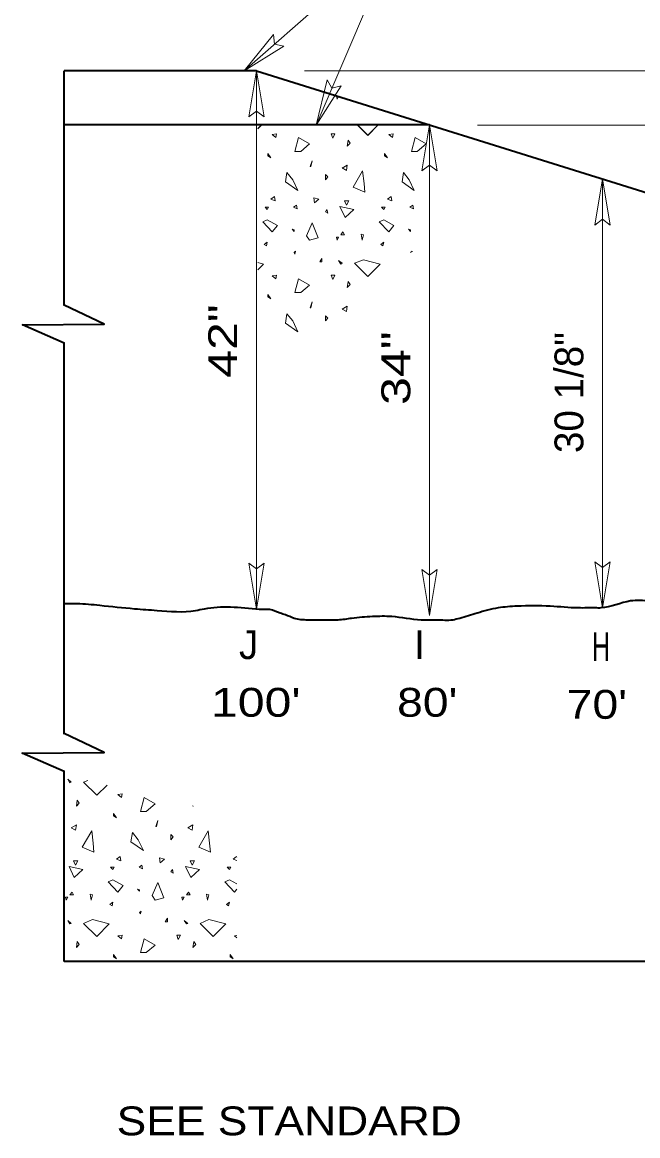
# Model space of a CAD drawing. Extents: x -15.1 to -7.9, y 13.6 to 23.8.
# Drawn here: x -15.003 to -13.723, y 19.682 to 21.999 of the extents above; entities that cross this region are included whole.
import ezdxf
from ezdxf.enums import TextEntityAlignment as Align

# ---------------------------------------------------------------- set-up
doc = ezdxf.new("R2010")
doc.units = 0
doc.header["$LTSCALE"] = 0.024
for name, color, linetype, lineweight in [('1', 7, 'Continuous', 35), ('10', 7, 'Continuous', 13), ('12', 7, 'Continuous', 53), ('6', 7, 'Continuous', 13)]:
    doc.layers.add(name, color=color, linetype=linetype, lineweight=lineweight)

msp = doc.modelspace()

# ---------------------------------------------------------------- linework, layer by layer
at = {"layer": '1'}
for p, q in [((-14.51633, 21.89767), (-14.91633, 21.89767)), ((-14.51633, 21.89767), (-11.27283, 20.88417)), ((-14.15633, 21.78517), (-14.91633, 21.78517)), ((-14.1535, 21.78433), (-14.15333, 21.78433)), ((-11.993, 20.044), (-14.91633, 20.044))]:
    msp.add_line(p, q, dxfattribs=at)
for points in [[(-14.51033, 20.77633), (-14.57033, 20.78117), (-14.62483, 20.77767), (-14.64283, 20.774), (-14.72267, 20.774), (-14.76967, 20.77767), (-14.84217, 20.78483), (-14.88933, 20.7885), (-14.91633, 20.7885)], [(-11.993, 20.76417), (-12.053, 20.769), (-12.1075, 20.7655), (-12.1255, 20.76183), (-12.20533, 20.76183), (-12.25233, 20.7655), (-12.32483, 20.77267), (-12.372, 20.77633), (-12.41917, 20.77633), (-12.46267, 20.77633), (-12.5025, 20.77267), (-12.58583, 20.7655), (-12.6185, 20.7655), (-12.65833, 20.7655), (-12.6945, 20.7655), (-12.72717, 20.77267), (-12.7635, 20.77633), (-12.78883, 20.77983), (-12.84683, 20.79067), (-12.883, 20.79067), (-12.93017, 20.79433), (-12.96283, 20.79067), (-13.028, 20.77983), (-13.0425, 20.77983), (-13.09317, 20.77633), (-13.11867, 20.77633), (-13.1585, 20.77633), (-13.202, 20.7835), (-13.23817, 20.79067), (-13.28167, 20.79433), (-13.32883, 20.79067), (-13.3615, 20.79067), (-13.41217, 20.77633), (-13.43033, 20.77633), (-13.47017, 20.77267), (-13.52083, 20.77983), (-13.5535, 20.7835), (-13.61517, 20.78717), (-13.64417, 20.79067), (-13.6985, 20.79433), (-13.73833, 20.79433), (-13.8, 20.77983), (-13.81083, 20.77983), (-13.84717, 20.77983), (-13.90517, 20.7835), (-13.974, 20.7835), (-14.01383, 20.77983), (-14.05733, 20.769), (-14.0935, 20.75817), (-14.108, 20.75467), (-14.14067, 20.75467), (-14.17333, 20.75467), (-14.23483, 20.76183), (-14.27483, 20.76183), (-14.31833, 20.75817), (-14.34717, 20.75467), (-14.369, 20.75467), (-14.40883, 20.75467), (-14.43783, 20.75817), (-14.456, 20.7655), (-14.46683, 20.769), (-14.48867, 20.77633), (-14.50317, 20.77633), (-14.51033, 20.77633)]]:
    msp.add_spline(points, degree=3, dxfattribs=at)
at = {"layer": '10'}
for p, q in [((-14.22542, 22.17525), (-14.54208, 21.89767)), ((-14.22542, 22.17525), (-14.39208, 21.78433)), ((-14.48042, 21.973), (-14.54208, 21.89767)), ((-14.48042, 21.973), (-14.47892, 21.953)), ((-14.45933, 21.94892), (-14.54208, 21.89767)), ((-14.45933, 21.94892), (-14.47892, 21.953)), ((-14.53233, 21.80167), (-14.51633, 21.89767)), ((-14.50033, 21.80167), (-14.51633, 21.89767)), ((-14.51633, 20.77725), (-14.51633, 21.89767)), ((-14.41633, 21.89767), (-9.09375, 21.89767)), ((-14.36917, 21.87892), (-14.39208, 21.78433)), ((-14.36917, 21.87892), (-14.35917, 21.86158)), ((-14.33975, 21.86633), (-14.39208, 21.78433)), ((-14.33975, 21.86633), (-14.35917, 21.86158)), ((-14.53233, 21.80167), (-14.51633, 21.81367)), ((-14.50033, 21.80167), (-14.51633, 21.81367)), ((-14.17233, 21.68917), (-14.15633, 21.78517)), ((-14.15633, 20.76417), (-14.15633, 21.78517)), ((-14.14033, 21.68917), (-14.15633, 21.78517)), ((-14.05633, 21.78433), (-9.13367, 21.78433)), ((-14.17233, 21.68917), (-14.15633, 21.70117)), ((-14.14033, 21.68917), (-14.15633, 21.70117)), ((-13.81233, 21.57667), (-13.79633, 21.67267)), ((-13.78033, 21.57667), (-13.79633, 21.67267)), ((-13.79633, 20.78), (-13.79633, 21.67267)), ((-13.81233, 21.57667), (-13.79633, 21.58867)), ((-13.78033, 21.57667), (-13.79633, 21.58867)), ((-13.81233, 20.876), (-13.79633, 20.78)), ((-13.81233, 20.876), (-13.79633, 20.864)), ((-13.78033, 20.876), (-13.79633, 20.78)), ((-13.78033, 20.876), (-13.79633, 20.864)), ((-14.53233, 20.87325), (-14.51633, 20.77725)), ((-14.53233, 20.87325), (-14.51633, 20.86125)), ((-14.50033, 20.87325), (-14.51633, 20.77725)), ((-14.50033, 20.87325), (-14.51633, 20.86125)), ((-14.17233, 20.86017), (-14.15633, 20.76417)), ((-14.17233, 20.86017), (-14.15633, 20.84817)), ((-14.14033, 20.86017), (-14.15633, 20.76417)), ((-14.14033, 20.86017), (-14.15633, 20.84817))]:
    msp.add_line(p, q, dxfattribs=at)
at = {"layer": '10', "lineweight": 35}
for p, q in [((-14.91633, 21.40933), (-14.91633, 21.89767)), ((-14.91633, 20.51733), (-14.91633, 21.332)), ((-14.91633, 20.044), (-14.91633, 20.44067))]:
    msp.add_line(p, q, dxfattribs=at)
for points in [[(-14.91583, 21.33067), (-15.003, 21.36883), (-14.83267, 21.37017), (-14.91583, 21.40967)], [(-14.916, 20.4395), (-15.00317, 20.47767), (-14.83283, 20.479), (-14.916, 20.5185)]]:
    msp.add_lwpolyline(points, dxfattribs=at)
at = {"layer": '6'}
for p, q in [((-14.50633, 21.78433), (-14.5135, 21.77717)), ((-14.50517, 21.78517), (-14.51333, 21.77692))]:
    msp.add_line(p, q, dxfattribs=at)
for points in [[(-14.3475, 21.84492), (-14.35, 21.84492), (-14.35, 21.84492), (-14.34867, 21.83875), (-14.34567, 21.84433)], [(-14.26292, 21.78517), (-14.28483, 21.76308), (-14.30675, 21.78517)], [(-14.26333, 21.78483), (-14.28483, 21.76333), (-14.30633, 21.78483)], [(-14.19267, 21.52117), (-14.19233, 21.5225), (-14.1955, 21.51967)], [(-14.51333, 21.49867), (-14.50133, 21.4955), (-14.51333, 21.48333)], [(-14.82692, 20.41142), (-14.84825, 20.39008), (-14.87575, 20.41742), (-14.86692, 20.42108)], [(-14.64842, 20.36825), (-14.64842, 20.36742), (-14.64775, 20.36808)], [(-14.55708, 20.26108), (-14.55742, 20.26292), (-14.56492, 20.25692), (-14.55708, 20.25408)], [(-14.55708, 20.20558), (-14.57258, 20.21442), (-14.58192, 20.21008), (-14.56208, 20.18875), (-14.55708, 20.19492)], [(-14.55708, 20.09858), (-14.56208, 20.09775), (-14.55708, 20.09375)]]:
    msp.add_lwpolyline(points, dxfattribs=at)
for points in [[(-14.48333, 21.76483), (-14.47567, 21.75867), (-14.47433, 21.76633)], [(-14.42417, 21.72983), (-14.40583, 21.74533), (-14.4285, 21.75867), (-14.43617, 21.72983)], [(-14.3605, 21.76633), (-14.35767, 21.75733), (-14.353, 21.76633)], [(-14.241, 21.76483), (-14.23333, 21.75867), (-14.232, 21.76633)], [(-14.18183, 21.72983), (-14.1635, 21.74533), (-14.18617, 21.75867), (-14.19383, 21.72983)], [(-14.3255, 21.753), (-14.32733, 21.74067), (-14.32117, 21.74683)], [(-14.49233, 21.7255), (-14.49233, 21.72083), (-14.48617, 21.7165)], [(-14.40433, 21.69817), (-14.403, 21.69817), (-14.40017, 21.7105)], [(-14.25, 21.7255), (-14.25, 21.72083), (-14.24383, 21.7165)], [(-14.33783, 21.69533), (-14.32883, 21.69067), (-14.32733, 21.7015)], [(-14.33783, 21.69508), (-14.32883, 21.69042), (-14.32733, 21.70125)], [(-14.2925, 21.66333), (-14.291, 21.64533), (-14.31517, 21.65567), (-14.29533, 21.68917)], [(-14.453, 21.686), (-14.45583, 21.6665), (-14.43033, 21.64817), (-14.44083, 21.67083)], [(-14.37267, 21.68167), (-14.37267, 21.67083), (-14.368, 21.677)], [(-14.37267, 21.68142), (-14.37267, 21.67058), (-14.368, 21.67675)], [(-14.21067, 21.686), (-14.2135, 21.6665), (-14.188, 21.64817), (-14.1985, 21.67083)], [(-14.4785, 21.63633), (-14.48617, 21.63017), (-14.47717, 21.627)], [(-14.43933, 21.61367), (-14.43183, 21.61033), (-14.43317, 21.61783)], [(-14.39683, 21.633), (-14.39533, 21.62267), (-14.38633, 21.63017)], [(-14.33317, 21.627), (-14.32883, 21.61783), (-14.32417, 21.627)], [(-14.23633, 21.63633), (-14.24383, 21.63017), (-14.23483, 21.627)], [(-14.197, 21.61367), (-14.1895, 21.61033), (-14.19083, 21.61783)], [(-14.49833, 21.61367), (-14.49367, 21.60883), (-14.49083, 21.61367)], [(-14.37267, 21.60417), (-14.368, 21.60133), (-14.3695, 21.60883)], [(-14.3425, 21.615), (-14.33167, 21.59233), (-14.31367, 21.60883)], [(-14.256, 21.61367), (-14.25133, 21.60883), (-14.2485, 21.61367)], [(-14.503, 21.58333), (-14.48333, 21.56217), (-14.4725, 21.5755), (-14.49367, 21.58767)], [(-14.40583, 21.54517), (-14.38783, 21.54983), (-14.40017, 21.5815), (-14.412, 21.5545)], [(-14.26067, 21.58333), (-14.241, 21.56217), (-14.23017, 21.5755), (-14.25133, 21.58767)], [(-14.43783, 21.5665), (-14.44217, 21.56783), (-14.43783, 21.5635)], [(-14.35, 21.55133), (-14.34867, 21.54517), (-14.34533, 21.55133)], [(-14.33633, 21.56217), (-14.33317, 21.556), (-14.34067, 21.556)], [(-14.2985, 21.5575), (-14.29667, 21.54517), (-14.29383, 21.556)], [(-14.1955, 21.5665), (-14.19983, 21.56783), (-14.1955, 21.5635)], [(-14.49983, 21.53617), (-14.4955, 21.53333), (-14.49367, 21.54083)], [(-14.2575, 21.53617), (-14.25317, 21.53333), (-14.25133, 21.54083)], [(-14.43467, 21.5225), (-14.43783, 21.51967), (-14.43617, 21.51633)], [(-14.38033, 21.50733), (-14.38467, 21.49983), (-14.38033, 21.49983)], [(-14.34067, 21.4955), (-14.33783, 21.497), (-14.34533, 21.503)], [(-14.29383, 21.5045), (-14.259, 21.4955), (-14.28483, 21.4695), (-14.31217, 21.497)], [(-14.48333, 21.471), (-14.47567, 21.46483), (-14.47433, 21.4725)], [(-14.42417, 21.43617), (-14.40583, 21.4515), (-14.4285, 21.46483), (-14.43617, 21.43617)], [(-14.3605, 21.4725), (-14.35767, 21.4635), (-14.353, 21.4725)], [(-14.3255, 21.45917), (-14.32733, 21.44683), (-14.32117, 21.453)], [(-14.49233, 21.43183), (-14.49233, 21.42717), (-14.48617, 21.42283)], [(-14.40433, 21.40433), (-14.403, 21.40433), (-14.40017, 21.41667)], [(-14.453, 21.39217), (-14.45583, 21.37267), (-14.43033, 21.35433), (-14.44083, 21.377)], [(-14.37267, 21.38783), (-14.37267, 21.377), (-14.368, 21.38317)], [(-14.33783, 21.4015), (-14.32883, 21.39683), (-14.32733, 21.40767)], [(-14.90408, 20.41608), (-14.90125, 20.41742), (-14.90875, 20.42358)], [(-14.80442, 20.39158), (-14.79692, 20.38542), (-14.79542, 20.39292)], [(-14.88908, 20.37958), (-14.89075, 20.36742), (-14.88475, 20.37358)], [(-14.74542, 20.35658), (-14.72692, 20.37208), (-14.74975, 20.38542), (-14.75725, 20.35658)], [(-14.81342, 20.35225), (-14.81342, 20.34758), (-14.80725, 20.34325)], [(-14.90125, 20.32208), (-14.89225, 20.31742), (-14.89075, 20.32825)], [(-14.72558, 20.32492), (-14.72408, 20.32492), (-14.72125, 20.33725)], [(-14.65892, 20.32208), (-14.64992, 20.31742), (-14.64842, 20.32825)], [(-14.85592, 20.29008), (-14.85442, 20.27192), (-14.87858, 20.28242), (-14.85875, 20.31592)], [(-14.77408, 20.31275), (-14.77708, 20.29325), (-14.75142, 20.27492), (-14.76192, 20.29758)], [(-14.69392, 20.30842), (-14.69392, 20.29758), (-14.68925, 20.30375)], [(-14.61358, 20.29008), (-14.61208, 20.27192), (-14.63625, 20.28242), (-14.61642, 20.31592)], [(-14.89658, 20.25358), (-14.89225, 20.24458), (-14.88758, 20.25358)], [(-14.79975, 20.26292), (-14.80725, 20.25692), (-14.79825, 20.25358)], [(-14.71792, 20.25975), (-14.71658, 20.24925), (-14.70758, 20.25692)], [(-14.65425, 20.25358), (-14.64992, 20.24458), (-14.64525, 20.25358)], [(-14.90592, 20.24175), (-14.89508, 20.21908), (-14.87708, 20.23558)], [(-14.81958, 20.24025), (-14.81492, 20.23558), (-14.81192, 20.24025)], [(-14.76042, 20.24025), (-14.75292, 20.23708), (-14.75442, 20.24458)], [(-14.69392, 20.23092), (-14.68925, 20.22808), (-14.69058, 20.23558)], [(-14.66358, 20.24175), (-14.65275, 20.21908), (-14.63475, 20.23558)], [(-14.57725, 20.24025), (-14.57258, 20.23558), (-14.56958, 20.24025)], [(-14.82425, 20.21008), (-14.80442, 20.18875), (-14.79358, 20.20208), (-14.81492, 20.21442)], [(-14.72692, 20.17192), (-14.70892, 20.17658), (-14.72125, 20.20825), (-14.73308, 20.18125)], [(-14.89975, 20.18875), (-14.89658, 20.18275), (-14.90408, 20.18275)], [(-14.86208, 20.18408), (-14.86025, 20.17192), (-14.85725, 20.18275)], [(-14.75908, 20.19308), (-14.76342, 20.19458), (-14.75908, 20.19025)], [(-14.65742, 20.18875), (-14.65425, 20.18275), (-14.66175, 20.18275)], [(-14.61975, 20.18408), (-14.61792, 20.17192), (-14.61508, 20.18275)], [(-14.91342, 20.17808), (-14.91208, 20.17192), (-14.90875, 20.17808)], [(-14.82092, 20.16292), (-14.81658, 20.16008), (-14.81492, 20.16758)], [(-14.67125, 20.17808), (-14.66975, 20.17192), (-14.66642, 20.17808)], [(-14.57858, 20.16292), (-14.57425, 20.16008), (-14.57258, 20.16758)], [(-14.75575, 20.14925), (-14.75908, 20.14642), (-14.75725, 20.14308)], [(-14.70142, 20.13408), (-14.70575, 20.12658), (-14.70142, 20.12658)], [(-14.90408, 20.12225), (-14.90125, 20.12358), (-14.90875, 20.12975)], [(-14.85725, 20.13125), (-14.82242, 20.12225), (-14.84825, 20.09625), (-14.87575, 20.12358)], [(-14.66175, 20.12225), (-14.65892, 20.12358), (-14.66642, 20.12975)], [(-14.61508, 20.13125), (-14.58008, 20.12225), (-14.60608, 20.09625), (-14.63342, 20.12358)], [(-14.80442, 20.09775), (-14.79692, 20.09158), (-14.79542, 20.09925)], [(-14.74542, 20.06275), (-14.72692, 20.07825), (-14.74975, 20.09158), (-14.75725, 20.06275)], [(-14.68158, 20.09925), (-14.67875, 20.09025), (-14.67408, 20.09925)], [(-14.88908, 20.08592), (-14.89075, 20.07358), (-14.88475, 20.07975)], [(-14.64675, 20.08592), (-14.64842, 20.07358), (-14.64242, 20.07975)], [(-14.81342, 20.05842), (-14.81342, 20.05375), (-14.80725, 20.04942)], [(-14.57108, 20.05842), (-14.57108, 20.05375), (-14.56492, 20.04942)]]:
    msp.add_lwpolyline(points, close=True, dxfattribs=at)

# ---------------------------------------------------------------- texts
at = {"layer": '12', "width": 1.3}
for s, height, p in [('42"', 0.06, (-14.55633, 21.33512)), ('34"', 0.06001, (-14.19633, 21.27887))]:
    msp.add_text(s, height=height, rotation=90, dxfattribs=at).set_placement(p, align=Align.CENTER)
at = {"layer": '12'}
msp.add_text('30 1/8"', height=0.06001, rotation=90, dxfattribs=at).set_placement((-13.83633, 21.228), align=Align.CENTER)
for s, height, p in [('J', 0.06, (-14.55242, 20.6735)), ('I', 0.06001, (-14.18833, 20.6735))]:
    msp.add_text(s, height=height, dxfattribs=at).set_placement(p)
for s, height, width, p in [('H', 0.06001, 0.65, (-13.81858, 20.66925)), ("100'", 0.06, 1.25, (-14.61083, 20.5535)), ("80'", 0.06001, 1.2, (-14.22375, 20.5535)), ("70'", 0.06001, 1.2, (-13.87092, 20.54925)), ('SEE STANDARD', 0.06001, 1.15, (-14.80692, 19.6825))]:
    msp.add_text(s, height=height, dxfattribs=dict(at, width=width)).set_placement(p)

doc.saveas('drawing.dxf')
